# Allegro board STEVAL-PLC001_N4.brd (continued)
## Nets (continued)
Q0.6: C48.2 J14.7 R66.1 U13.16 U13.17
Q0.7: C47.2 J14.8 R63.1 U13.18 U13.19
Q1.0: D16.C J13.1 R40.1 U8.14
Q1.1: D15.C J13.2 R45.1 U8.15
Q1.2: D14.C J11.1 R38.1 U8.16
Q1.3: D13.C J11.2 R37.1 U8.17
RCC_OSC32_IN: R173.2 U27.8
RCC_OSC32_OUT: R180.2 U27.9
RCC_OSC_IN: R178.2 U27.23
RCC_OSC_OUT/TEST: U27.24
RX_EXT: J25.5 R174.1 R175.1
SDO_DAISY: R75.1 R155.2 U2.2
SPI2_ISO_MOSI: R121.2 R154.2
SPI2_MISO: R21.1 R74.1 R126.2 U27.28
SPI2_MORPHO_ISO: J18.15 R72.1 R126.1
SPI2_NSS: R18.1 R68.1 R129.2 U27.73
SPI2_SCK: R69.1 R113.2 R190.2 TP9.1 U2.3 U27.74
SPI5_HOLD: U20.7 U27.36
SPI5_MISO: U20.2 U27.20
SPI5_MOSI: U20.5 U27.21
SPI5_NSS: U20.1 U27.18
SPI5_SCK: U20.6 U27.19
SPI5_WP: U20.3 U27.123
SYS_JTCLK-SWCLK: J23.4 U27.109
SYS_JTDI: J23.8 U27.110
SYS_JTDO-SWO: J23.6 U27.133
SYS_JTMS-SWDIO: J23.2 U27.105
SYS_JTRST: R191.1 U27.134
TX_EXT: J25.2 R177.2 U28.7
UART4-RX: J24.3 R96.2 R109.1
UART4-TX: J22.3 R106.1
UART5_RX: R104.2 R136.1 R138.1 U27.116
USART3_RX: J24.1 R176.2 U28.5
USART3_TX: J22.1 U28.1
USB.OTG_FS_DM: R161.2 U25.2
USB.OTG_FS_DP: R163.2 U25.1
USB.OTG_FS_ID: D44.C(CATHODE) R160.2 U22.4
USB.OTG_FS_VBUS: C92.1 D43.C D46.3 R148.1 R157.2 R192.1 U21.1(OUT) U22.5(VBUS)
USB.OVER_CURRENT: D41.C R146.2 U21.3 U27.87
USB.POWER_SWITCH_ON: R147.2 R192.2 U21.4 U27.88
VZ1: D23.C J12.2 U8.3 U8.18(VZ2)
N15104302: R39.1 U9.2
N15104306: R42.1 U9.3
N15104310: R48.1 U9.4
N15105235: D19.C R41.2 U9.7
N15105303: D20.C R43.2 U9.6
N15105538: R47.1 U8.12
N15105768: R44.1 U8.11
N15112703: D23.A J10.2 J12.1
N15122676: R86.2 U14.4 U15.1
N15122744: C63.1 C66.2 C128.2 D35.C TP11.1 U14.6(VO) U15.2
N15123033: C62.2 C64.2 C65.1 L1.2 L2.1 U14.1
N15123037: D35.A L2.2 U14.8
N15123750: R85.2 U14.2
N15125008: D9.C U3.1
N15125401: D12.C U6.4
N15133396: D17.C R33.2 TP7.1 U7.7
N15133410: D18.C R35.2 U7.6
N15220592: R76.2 R78.1 U13.32
N15439126: D24.A R63.2
N15439189: D25.A R66.2
N15439310: D26.A R67.2
N15439443: D28.A R70.2
N15439617: D30.A R73.2
N15439707: D31.A R77.2
N15439797: D32.A R79.2
N15439887: D33.A R80.2
N15474250: R25.2 U5.9
N15474355: C25.1 U5.10
N15474517: C27.1 U5.15(VBUF2)
N15476731: R23.2 U4.9
N15476759: C19.1 U4.10
N15476871: R24.2 U4.14
N15476899: C21.1 U4.15(VBUF2)
N15484919: R154.1 R155.1 R156.1 U27.27
N15485310: C111.1 C112.2 R168.1 U27.32
N15486514: C102.1 U27.71
N15487467: R157.1 R158.1 U27.101
N15487548: C101.2 U27.106
N15498231: C103.1 C104.1 C105.1 L6.2 R168.2 U27.33
N15498429: R172.2 U28.2
N15498461: R174.2 R175.2 U28.3
N15499136: C124.1 R173.1 Y1.2
N15499220: R178.1 Y2.3(OSC3)
N15499244: C125.1 R180.1 Y1.1
N15499420: R183.2 Y2.1
N15511092: Q1.3 R83.2 U14.7
N15516624: C54.2 R71.2 R72.2 TP10.1 U13.24
N15519714: C50.2 D27.C(CATHODE) R64.1 R65.1 SW1.2 U13.21
N15526476: R46.1 U9.1
N15526659: R32.1 U7.1
N15526663: R31.1 U7.2
N15526669: R34.1 U7.3
N15526673: R36.1 U7.4
N15644326: R71.1 R156.2
N15652884: C98.1 L7.2 U26.1 U26.3
N15653000: D48.A R150.2
N15853888: BT1.1 BT1.2 R184.2
N15937224: R163.1 R164.1 U27.104
N15989509: C53.2 R74.2 R75.2 U13.31
N15989570: C55.2 R68.2 U13.22
N15989574: C57.2 R69.2 U13.23
N16126417: R87.1 U15.5
N16126447: R89.1 U15.13
N16126488: R91.1 U15.21
N16126496: R90.2 U15.14
N16126511: R88.2 U15.6
N16423386: R92.2 U15.22
N16503177: D34.C R81.1
N16514344: C86.1 D39.1 F1.2 Q4.5 Q4.6 Q4.7 Q4.8
N16514352: C87.1 C90.1 D38.C(CATHODE) L4.1 Q4.1 Q4.2 Q4.3(S3) R144.1
N16514548: C90.2 D38.A Q4.4 R144.2 R145.2
N16561780: D11.C U6.1
N16578488: D10.C U3.4
N16596019: R61.1 U12.2
N16596025: R60.1 U12.3
N16605257: C100.2 R184.1 R185.1 U27.6
N16616858: D40.A R142.1
N16634792: D21.A R51.1
N16639460: R62.1 U12.1
N16639519: R59.1 U12.4
N16642965: R57.1 U11.2
N16642967: R58.1 U11.1
N16642969: R56.1 U11.3
N16642971: R55.1 U11.4
N16646826: R53.1 U10.2
N16646828: R50.1 U10.3
N16646830: R54.1 U10.1
N16646832: R49.1 U10.4
N16671237: D15.A R29.2
N16671239: D13.A R27.2
N16671241: D16.A R30.2
N16671243: D14.A R28.2
N16678102: D22.A R52.1
N16736638: D41.A R143.1
N16736836: U22.2 U25.5
N16736872: U22.3 U25.6
N16737152: D47.A R149.2
N16737156: Q5.1 R148.2 R151.1
N16737176: D47.C Q5.3
N16752352: J8.1 R37.2
N16753248: J9.1 R38.2
N16769682: D45.4(C) D46.4(C) L7.1
N16781010: R165.1 U27.48
N16815309: J18.1 R104.1
N16815311: J18.2 R115.2
N16815356: J18.3 R105.1
N16815358: J18.4 R106.2
N16815404: J18.5 R108.1
N16815406: J18.6 R109.2
N16815431: J17.14 R186.2
N16815500: J17.21 R95.1 R96.1
N16815530: J18.11 R113.1
N16815532: J18.12 R118.2
N16815574: J18.13 R121.1
N16815576: J18.14 R122.2
N16815612: J18.16 R123.2
N16815702: J18.19 R189.1
N16815735: J18.22 R131.2
N16815777: J18.24 R134.2
N16815800: J17.28 R187.2
N16815809: J18.26 R135.2
N16815841: J18.28 R136.2
N16815880: J18.30 R138.2
N16815921: J18.31 R190.1
N16815961: J17.35 R98.1
N16815963: J17.36 R188.2
N16815968: J18.34 R139.2
N16815983: J17.37 R99.1
N16816031: R101.1 U19.59
N16816085: R103.1 U19.56
N16816140: R116.1 U19.54
N16816178: R111.1 U19.53
N16816234: R117.1 U19.51
N16816260: R120.1 U19.50
N16816337: R125.1 U19.48
N16816363: R128.1 U19.47
N16816449: R133.1 U19.45
N16816548: D37.A R137.2
N16816568: D36.A R94.2
N16816730: D37.C Q3.3
N16816751: D36.C Q2.3
N16816773: Q2.1 R97.2 R102.1
N16816793: Q3.1 R140.2 R141.1
N16817624: J18.17 R129.1 R130.1
N16822475: C4.1 R1.1 U1.48(_CS)
N16822477: C3.1 R2.1 U1.47
N16822479: C2.1 R3.1 U1.46
N16822481: R4.1 U1.44
N16822499: D1.A U1.41
N16822523: D2.A U1.40
N16822549: R5.1 U1.42
N16822551: D3.A U1.39
N16822575: D4.A U1.38
N16822613: D5.A U1.37
N16822638: D6.A U1.36
N16822654: D7.A U1.35
N16822678: D8.A U1.34
N16822815: R6.1 U1.1
N16822888: J2.2 R8.2
N16822890: R8.1 U1.2
N16822932: R10.1 U1.4
N16823099: J4.2 R10.2
N16823193: C11.1 R13.2 U1.13
N16823195: R15.2 R16.1 U1.14
N16823486: R18.2 R20.2 U2.4
N16823562: R21.2 TP2.1 U2.7
N16919862: R161.1 R162.1 U27.103
N16919990: R152.1 R153.1 U27.35
N16946294: R159.1 R160.1 U27.102
N164994551: R26.2 U5.14
N164999121: D29.C R76.1
N165089721: Q1.1 R84.2
N170697731: J23.7 R191.2
N1681503127: R100.2 U19.28
N1681503130: R114.2 U19.31
N1681503132: R107.2 U19.33
N1681503133: R110.2 U19.34
N1681503135: R112.2 U19.36
N1681503136: R119.2 U19.37
N1681503138: R124.2 U19.39
N1681503139: R127.2 U19.40
N1681503141: R132.2 U19.42

Pads without a net: D45 1; D46 1; J17 1 2 3 4 6 7 9 10 11 12 13 15 17 18 19 23 24 25 26 27 29 30 31 32 38; J18 8 10 18 21 23 25 27 29 33 35 36 37 38; TP16 1; U1 45; U2 5 6 11 12; U4 1 12; U5 1 12; U13 2 26 27 28 29 30; U14 5; U15 41 42; U16 1 16; U19 14 30 57 69 70 73; U22 6 7 8; U24 3; U25 4; U26 4; U29 3

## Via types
v1: diameter 0.4, hole 0.15, TOP to BOTTOM, 414 vias
v2: diameter 0.61, hole 0.33, TOP to BOTTOM, 393 vias
v3: diameter 0.61, hole 0.33, TOP to POWER PLANE, 18 vias

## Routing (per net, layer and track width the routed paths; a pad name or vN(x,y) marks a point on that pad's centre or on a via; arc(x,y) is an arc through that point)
3V3: length 24.2
  POWER PLANE w0.5: v1(68.21,46.98) 67.76,46.52 58.99,46.52 v1(56.71,48.8)
  BOTTOM w0.4: C96.1 70.51,47.99 70.51,48.45 R150.1
  BOTTOM w0.5: v1(68.21,46.98) 68.21,47.79 68.81,48.39 L5.1 69.95,48.6 R150.1 ; v1(70.35,47.24) 70.71,47.6 C96.1 ; v1(56.71,48.8) 53.91,48.8 53.3,49.42 L6.1
  BOTTOM w0.7: U26.5 70.91,46.41 70.85,46.47 70.85,47.13 70.9,47.18 C96.1
5V: length 86.9
  TOP w0.152: v2(43.91,42.8) 43.97,42.86
  TOP w0.3: D45.3 86.51,37.4 v2(86.71,37.2)
  TOP w0.4: L1.1 41.57,41.3 43.13,42.86 43.48,42.86 43.83,42.86 43.97,42.86
  TOP w0.5: U24.6 92.45,30.08 92.45,30.94 93.42,31.92 ; v2(86.71,37.2) 84.79,37.2 84.36,36.77 v2(78.24,36.77)
  BOTTOM w0.3: v2(43.91,42.8) 44.11,43 44.51,43 44.81,43.3 R83.1
  BOTTOM w0.4: v2(43.91,42.8) 43.91,38.6 47.46,35.05 50.42,35.05 57.32,28.15 90.52,28.15 90.76,28.39
  BOTTOM w0.5: v2(86.71,37.2) 89.51,34.4 89.51,31.33 U24.6 90.76,28.39 ; v2(78.24,36.77) 77.95,36.77 77.93,36.75 U21.5
5V_FIELD: length 58.1
  TOP w0.25: D42.C 60.73,19.6 60.34,20 v1(60.34,20.52)
  TOP w0.3: v1(64.29,24.4) 64.32,24.4 C40.1 R52.2 C31.2 R51.2 C35.2 ; D42.C 66.21,20.63 v1(66.44,20.86)
  TOP w0.4: D42.C 66.11,19.5 66.11,18.02 v2(65.89,17.8)
  TOP w0.5: D42.C 67.25,19.6 v2(67.58,19.28)
  BOTTOM w0.25: v1(66.44,20.86) 66.31,20.99 R55.2 ; R59.2 59.87,20.99 v1(60.34,20.52)
  BOTTOM w0.3: 73.31,18.2 72.97,18.2 72.96,18.21 72.46,18.21 72.45,18.2 72.25,18.2 C94.2 ; 64.57,21.91 C43.1 64.65,21.91 65.16,21.4 65.31,21.4 65.72,20.99 R55.2 ; 64.57,21.91 65.11,22.45 65.11,23.58 v1(64.29,24.4) ; 64.57,21.91 64.43,21.91 R62.2 ; R54.2 75.27,20.08 75.3,20.08 75.66,19.73 C95.1 ; v2(67.58,19.28) 67.58,19.38 68.65,20.45 68.74,20.45 69,20.71 69.33,21.04 R58.2 R49.2
  BOTTOM w0.4: U23.3 73.62,17.89 72.91,18.6 72.76,18.6 69.71,18.6 68.91,17.8 v2(65.89,17.8)
  BOTTOM w0.5: C95.1 77.81,21.67 U9.8 77.81,25.9 78.31,26.4 83.56,26.4 84.06,25.9 U7.8
  BOTTOM w0.6: U23.3 75.86,18.84 C95.1
24V: length 13.4
  TOP w1.2: C84.1 15.26,15.95 15.26,18.14
  TOP w3: J19.2 13.11,5.66 C84.1
24V_FIELD: length 97.6
  TOP w0.152: L4.2 13.01,53.6 ; v2(14.88,56.14) 13.26,56.14 13.01,55.89 ; v2(13.01,56.12) 12.43,56.12 12.41,56.09 v2(11.13,56.09) ; 13.01,53.6 v2(11.17,51.76) ; 13.01,53.6 13.01,53.5 ; 13.01,53.49 v2(14.83,51.67) ; v2(77.31,17.6) 78.08,18.37 78.08,18.44 ; 78.08,18.44 v2(78.91,17.6) ; 78.08,18.44 78.08,19.26 ; 13.01,53.47 13.01,52.56
  TOP w0.2: U8.13 69.53,14.93 v1(69.66,14.8)
  TOP w0.3: v1(73.95,14.01) 73.83,13.89 C36.2 73.2,13.86 C34.2 ; 33.57,102.21 33.57,104.14 v1(33.11,104.6) ; 33.57,102.21 R15.1 ; 33.57,102.21 34.87,102.21 R13.1 ; v1(68.47,11.48) 68.29,11.66 R30.1 ; v2(72.51,11.2) 72.67,11.36 72.67,11.49 R29.1 ; C46.2 42.7,22.79 41.61,21.7 U13.TAB4
  TOP w0.4: C89.1 v2(13.01,51.8)
  TOP w0.5: 78.08,20.14 C37.1 79.62,22.2 v2(79.91,22.2) ; 78.08,20.14 78.08,19.26 ; 78.08,20.14 78.82,20.14 ; L4.2 13.01,54.9 ; 13.01,54.9 v2(13.01,56.12) ; 13.01,54.9 12.6,55.31 11.91,55.31 v2(11.13,56.09) ; 13.01,54.9 13.37,55.26 14,55.26 v2(14.88,56.14) ; 78.08,19.26 77.97,19.26 77.31,18.6 v2(77.31,17.6) ; 78.08,19.26 78.08,19.26 78.91,18.43 v2(78.91,17.6) ; R27.1 83.57,11.91 82.95,11.29 79.76,11.29 78.85,12.2 R28.1 77.87,12.68 77.57,12.98 v1(77.06,12.98) ; v2(13.01,51.8) 13.01,52.56 12.85,52.72 12.85,53.31 13.01,53.47 13.01,53.5 12.06,53.5 11.17,52.61 v2(11.17,51.76) ; v2(8.46,60.02) 7.88,60.02 R142.2 ; J26.2 88.67,11.07 88.49,11.25 C130.1 ; 13.01,53.63 13.16,53.48 13.81,53.48 14.83,52.46 v2(14.83,51.67)
  BOTTOM w0.152: 20.69,30.34 19.77,30.34 19.51,30.6
  BOTTOM w0.3: v2(72.51,11.2) 69.3,11.2 69.02,11.48 v1(68.47,11.48)
  BOTTOM w0.5: v2(21.51,29.52) 19.84,31.19 ; C88.1 19.41,30.75 19.84,31.19 ; C88.1 18.46,30.7 18.09,31.07 17.92,31.07 v2(17.25,31.74) ; C88.1 19.51,30.6 19.51,29.64 v2(20.62,28.53) ; v2(7.51,56.93) 7.51,57.46 6.46,58.52 6.87,58.92 ; v1(77.06,12.98) 76.83,12.98 76.66,12.81 U23.1 74.23,12.14 C93.1 74.23,9.94 74.58,9.59 v2(74.58,8.15) ; 6.87,58.92 v2(6.87,60.1) ; 6.87,58.92 7.36,58.92 v2(8.46,60.02) ; 19.84,31.19 19.66,31.37 19.66,31.4 v2(18.29,32.77)
  vias: v2(17.16,22.05) v2(17.22,20.81) v2(17.22,19.6) v2(17.22,18.38) v2(17.24,17.1) v2(17.21,16.09) v2(18.36,22.05) v2(18.41,20.81) v2(18.44,19.6) v2(18.41,18.38) v2(18.42,17.1) v2(18.42,16.09) v2(19.56,22.05) v2(19.62,20.81) v2(19.62,19.6) v2(19.62,18.38) v2(19.64,17.1) v2(19.61,16.09) v2(20.76,22.05) v2(20.81,20.81) v2(20.84,19.6) v2(20.81,18.38) v2(20.82,17.1) v2(20.82,16.09) v2(22.01,22.1) v2(22.01,16.09) v2(22.07,20.86) v2(22.07,19.65) v2(22.07,18.43) v2(22.11,17.2) v2(23.21,22.1) v2(23.26,20.86) v2(23.26,18.43) v2(23.26,16.04) v2(23.29,19.65) v2(23.31,17.2) v2(24.41,22.1) v2(24.47,20.86) v2(24.47,19.65) v2(24.47,18.43) v2(24.51,17.2) v2(24.47,16.04) v2(25.61,22.1) v2(25.66,20.86) v2(25.66,18.43) v2(25.66,16.04) v2(25.69,19.65) v2(25.71,17.2) v2(26.86,22) v2(26.92,20.76) v2(26.92,19.55) v2(26.92,18.33) v2(26.87,17.05) v2(26.87,16.04) v2(28.06,16.04) v2(28.06,22) v2(28.11,20.76) v2(28.14,19.55) v2(28.11,18.33) v2(28.09,17.05) v2(29.26,22) v2(29.32,20.76) v2(29.32,19.55) v2(29.32,18.33) v2(29.34,17.05) v2(29.31,16.04) v2(30.46,22) v2(30.51,20.76) v2(30.54,19.55) v2(30.51,18.33) v2(30.52,17.05) v2(30.52,16.04) v2(31.61,22.05) v2(31.66,20.81) v2(31.66,18.38) v2(31.69,19.6) v2(31.67,17.1) v2(31.67,16.09) v2(34.77,23.39) v2(34.77,22.17) v2(34.77,20.95) v2(34.77,19.94) v2(35.98,23.39) v2(35.98,21.97) v2(35.98,19.94) v2(36.59,20.75) v2(37,19.94) v2(37.61,23.39) v2(37.81,21.56) v2(37.81,20.75) v2(39.03,23.39) v2(39.23,22.37) v2(39.23,20.95) v2(39.43,19.94) v2(40.45,23.39) v2(40.65,22.17) v2(40.65,20.95) v2(40.65,19.94)
GND_CLT1: length 41.5
  TOP w0.2: v1(28.71,91.6) 28.61,91.5 C1.2 28.69,91.01 C2.2 ; v1(27.71,91.86) 27.8,91.95 U1.43 ; v1(26.51,90.2) 26.95,90.2 R5.2 ; C4.2 33.92,93.14 C6.1 v1(34.51,93.18)
  TOP w0.3: v1(32.11,91.6) 32.12,91.59 C3.2 ; TP14.1 25.48,88.71 R5.2 25.94,90.19 25.61,89.86 22.45,89.86 v1(18.62,93.69)
  TOP w0.5: C14.2 v1(46.76,91.71) 46.76,95.14 47.99,96.37 TP4.1 ; v1(39.83,97.44) v1(39.83,95.86) C5.2
  BOTTOM w0.2: v1(28.71,91.6) 28.45,91.86 v1(27.71,91.86) 26.51,90.66 v1(26.51,90.2)
  BOTTOM w0.3: R194.1 20.07,95.02 19.95,95.02 v1(18.62,93.69) ; C129.2 33.9,93.79 v1(34.51,93.18) 33.69,93.18 v1(32.11,91.6)
  BOTTOM w0.4: v2(38.71,94.87) 38.71,94.4 38.77,94.34 U2.9
GND_EARTH: length 28.9
  TOP w3: C84.2 3.11,18.23 3,18.35 3,20.95 3.11,21.07 C91.1
  BOTTOM w3: J20.1 3.01,11.75 3.11,11.85 C84.2 C91.1
GND_EXT: length 17.4
  TOP w0.3: 89.41,86.85 v2(90.22,86.85) 90.22,87.7 91.49,88.98 94.62,88.98
  TOP w0.4: 94.62,88.98 95.71,88.98 J25.4 J25.3
  BOTTOM w0.152: R177.1 v2(90.22,86.85)
  BOTTOM w0.3: U28.4 91.06,93.5 93.05,91.52 94.79,91.52
  BOTTOM w0.4: 94.79,91.52 95.71,91.52 J25.3
GND_FIELD: length 321.5
  TOP w0.152: 6.51,19.65 v2(7.6,19.65) 7.6,19.81 7.67,19.88 ; 6.51,19.65 6.15,19.65 ; 6.51,19.65 6.51,19.5 7.1,18.91 v2(7.73,18.91) ; 27.32,98.12 27.32,97.64 26.8,97.12 26.8,96.61 U1.49 29,97.31 29,98.12 29.3,98.42
  TOP w0.2: 29.3,98.42 29.3,99.25 29.31,99.26 ; 27.8,93.33 27.55,93.57 27.55,94.07 27.8,94.32 27.8,94.75 27.55,95 U1.49 28.93,94.48 29.85,94.48 30.21,94.11 U1.3 ; C11.2 31.97,98.34 31.74,98.11 U1.11 U1.12 ; U13.3 33.36,20.65 32.91,20.2 v2(32.91,19.05) ; 26.8,99.25 26.8,98.64 27.32,98.12 ; 71.58,12.94 R45.2
  TOP w0.3: 71.57,12.94 71.51,12.94 71.49,12.92 ; 71.57,12.94 C34.1 ; 71.57,12.94 71.71,12.8 v1(71.71,12.39) ; C12.1 v1(24.66,102.78) ; C18.1 19.96,102.55 19.91,102.6 v1(19.91,102.87) ; C13.1 v1(23.11,102.85) ; C34.1 72.59,12.94 ; C34.1 72.44,12.97 C36.1 ; C86.2 3.1,42.99 2.51,42.4 v2(2.51,42.3) ; v1(66.66,13.55) 67.06,13.14 R40.2 ; C17.1 v1(21.56,102.85) ; C46.1 v2(43.71,24.5) ; C7.1 v1(31.11,102.6) ; R16.2 v1(32.76,102.65) ; C9.1 v1(27.91,102.78) ; C10.1 v1(26.31,102.75) ; C8.1 v1(29.51,102.6) ; U8.20 74.09,16.21
  TOP w0.35: U8.20 U8.19
  TOP w0.4: D33.C D32.C D31.C 35.08,13.8 ; 85.21,18.7 84.45,19.46 C37.2 83.7,21.4 v2(82.71,21.4) ; D28.C 40.06,14.6 39.91,14.75 C49.1 ; D28.C D30.C 35.16,14.83 35.71,15.38 C58.1 ; D28.C D26.C D25.C ; R195.2 v1(89.73,23.29)
  TOP w0.5: v2(13.91,49.8) 13.8,49.69 C89.2 ; D8.C D7.C D6.C D5.C 32.58,107 32.53,107.05 D4.C D3.C 26.14,107.05 25.69,106.6 v1(25.51,106.6) ; D24.C 55.16,14.15 v2(54.51,14.8) ; v2(2.87,45.6) 2.91,45.6 2.92,45.59 R145.1 ; v2(46.23,12.99) 45.41,13.8 ; v2(86.03,22.4) 84.45,20.82 C37.2 ; 74.09,21.24 U8.1 73.75,21.48 ; v2(64.93,14.8) 64.93,14.82 65.41,15.3 D42.A ; C87.2 5.18,39.86 6.51,41.2 v2(6.51,41.8) ; C87.2 4.4,39.98 4.4,41.11 4.04,41.46 v2(3.59,41.46) ; C87.2 5.18,37.93 ; v1(22.46,106.95) 22.31,107.1 D2.C 17.27,107.1 17.23,107.15 D1.C ; 37.68,25.02 U13.TAB2 37.94,25.02 ; v3(33.31,15.35) 33.51,15.15 33.73,15.15 35.08,13.8 D30.C ; J26.1 83.59,8.73 86.99,12.13 C130.2 ; 5.18,37.93 v2(6.51,36.6) ; 5.18,37.93 5.18,37.86 3.91,36.6 v2(3.73,36.6) ; 73.75,21.48 73.75,21.41 74.51,20.65 v1(74.51,19.8) 74.51,16.24 U8.20 v2(74.53,15.82) ; 73.75,21.48 U8.2 ; C47.1 C48.1 C49.1 C51.1 C52.1 C56.1 C58.1 C59.1 ; D40.C 7.21,63.9 6.91,63.6 6.91,63.3 v2(6.74,63.3) ; 24.66,13.8 v2(24.01,13.15)
  TOP w1: 6.15,19.65 6.15,21.98 v2(6.11,22.01) ; U13.TAB3 v2(42.11,25.02) ; U13.TAB1 v2(33.51,25.02)
  TOP w1.4: U13.TAB1 37.68,25.02 ; U13.TAB3 37.94,25.02
  TOP w3: 6.15,19.65 8.02,17.78 J19.1
  POWER PLANE w0.5: 4.9,36.88 5.18,37.15 5.18,40.46 v2(6.51,41.8) ; 4.9,37.72 6.02,36.6 v2(6.51,36.6) ; 4.9,37.72 4.9,40.61 4.04,41.46 v2(3.59,41.46) ; 4.9,37.72 3.79,36.6 v2(3.73,36.6)
  POWER PLANE w1: 4.9,37.72 4.9,32.41 6.11,31.2 14.91,31.2 15.31,30.8 15.31,30.4 14.91,30 5.11,30 4.71,29.6 4.71,29.2 5.11,28.8 16.11,28.8 16.51,28.4 16.51,27.8 16.31,27.6 6.71,27.6 6.31,27.2 6.31,26.8 6.71,26.4 10.71,26.4 11.11,26 11.11,25.4 10.71,25 8.31,25 8.11,24.8 8.11,24 6.83,22.72 6.82,22.72 v2(6.11,22.01)
  LOGIC_PLANE w1: 6.11,21.28 v2(6.11,22.01)
  BOTTOM w0.152: 15.41,34.7 15.87,34.24 16.42,34.24 v2(17.18,35) ; 15.41,34.7 15.11,35 ; 15.41,34.7 15.41,33.74 ; v2(14.31,37.64) 14.54,37.64 15.69,36.5 15.69,36.17 C88.2
  BOTTOM w0.3: R194.2 22.15,95.59 21.98,95.59 21.98,95.64 ; C94.1 73.03,16.94 73.69,16.28 74.07,16.28 v2(74.53,15.82) ; 25.52,95.19 v2(25.52,95.04)
  BOTTOM w0.5: 25.12,95.59 22.15,95.59 ; v1(25.51,106.6) 23.46,106.6 23.11,106.95 v1(22.46,106.95) 20.66,106.95 17.11,103.4 17.11,100.4 21.92,95.58 R194.2 ; v2(12.45,35.61) 13.37,35.61 13.38,35.6 14.51,35.6 ; 15.11,35 C88.2 14.51,35.6 ; 15.11,35 15.08,34.97 15.08,34.07 15.41,33.74 v2(15.41,32.86) ; 15.11,35 v2(17.18,35) ; 14.51,35.6 14.31,35.8 v2(14.31,37.64) ; C85.2 6.46,64.05 6.74,63.77 v2(6.74,63.3) ; C85.2 6.46,65.95 6.91,66.4 v2(6.91,66.47) ; C85.2 7.79,64.88 ; v2(9.22,66) 8.91,66 7.79,64.88 ; 7.79,64.88 v2(9.23,64.88) ; v2(15.71,23.85) 17.19,23.85 18.23,24.89 ; 18.23,24.89 C45.2 20.4,24.89 21.24,25.73 v2(21.24,26.6) ; 18.23,24.89 17.36,25.75 v2(17.36,26.55) ; v2(76.66,11.45) 75.98,10.78 C93.2
  BOTTOM w0.8: 25.52,95.19 25.12,95.59 25.12,96.01 25.71,96.6
  vias: v2(25.52,97.88) v2(25.51,96.35) v2(25.52,93.82) v2(26.74,97.88) v2(26.74,95.04) v2(26.74,93.82) v2(26.91,96.35) v2(28.16,97.88) v2(28.16,96.46) v2(28.16,95.24) v2(28.16,93.82) v2(29.58,97.88) v2(29.58,96.66) v2(29.58,95.24) v2(29.58,93.82) v2(82.61,19.5) v2(82.67,18.26) v2(83.71,20.6) v2(83.81,19.5) v2(83.86,18.26) v2(85.01,19.5) v2(85.07,18.26) v2(85.31,20.6) v2(86.21,19.5) v2(86.26,18.26)
GND_LCD: length 23.3
  TOP w0.152: 32.46,38.72 U14.9
  TOP w0.2: 30.11,38.72 29.89,38.5 29.85,38.5 R86.1 ; 30.11,38.72 29.96,38.72 29.6,39.09 R85.1 ; 30.11,38.72 U14.3
  TOP w0.3: C66.1 v1(36.37,42.34) 36.36,42.35 ; R86.1 R85.1 ; 32.46,38.21 32.46,37.73 32.16,37.43 30.67,37.43 v2(29.59,36.35) ; 32.46,38.21 32.46,38.72 ; 32.46,38.21 33.02,37.65 33.37,37.65 v2(33.83,37.19) ; C128.1 34.56,45.25 34.31,45 v1(34.31,44.7) ; v1(37.86,43.5) 38.63,42.73 Q1.2 39.01,42.73 39.38,42.37 39.38,40.84 39.37,40.84 C62.1 C64.1 39.37,38.09 L3.2 39.76,37.65 39.14,37.03 39.14,36.98 38.46,36.3 C65.2
  TOP w0.4: C63.2 33.08,45.39 C128.1 ; U14.9 32.14,38.72 U14.3
GND_LOGIC: length 321.4
  TOP w0.152: v1(40.31,33.28) C57.1 ; v1(44.91,33.31) 44.91,32.72 ; v1(41.21,33.28) C55.1 ; C53.1 34.66,32.79 v1(34.09,32.22) ; C50.1 v1(43.06,33.28)
  TOP w0.16: v3(46.33,59.83) 46.32,59.82 46.05,59.82 45.84,59.61 45.83,59.61 45.66,59.45 45.66,59.43 45.47,59.24 U17.17 ; U15.3 v1(44.39,51.82)
  TOP w0.2: U13.1 v2(33.06,29.05) ; C54.1 v1(38.66,33.28)
  TOP w0.22: v1(39.11,89.4) 38.15,90.36 36.27,90.36 v1(35.7,89.79)
  TOP w0.25: 93.83,52.31 U22.1 v3(94.96,52.3) 95.89,52.3 96.4,51.79 96.4,50.92 v1(95.8,50.32)
  TOP w0.3: v2(38.01,58.05) 37.36,57.39 D49.A 36.55,57.42 36.05,57.92 36.05,58.16 35.07,59.15 ; v1(62.86,62.88) 62.77,62.88 62.45,63.2 C127.1 ; C67.1 36.25,46.94 36.11,46.8 v1(35.51,46.8) ; U15.36 60.89,51.96 60.52,51.59 v1(60.31,51.59) ; U15.35 60.39,52.19 60.34,52.14 60.34,52.06 60.16,51.89 60.05,51.89 59.76,51.6 v1(59.11,51.6) 57.63,51.6 57.39,51.84 U15.29 ; U16.17 v1(51.82,59.73) ; v2(89.11,49.8) 89.11,51.91 89.48,52.28 D43.A ; C103.2 v1(56.92,65.61) ; L3.1 40.37,36.71 v1(40.37,36.85) ; 93.83,52.31 93.59,52.31
  TOP w0.4: v2(51.17,31.46) SW1.1 ; SW1.1 v2(51.17,28.25) ; SW1.1 v2(49.81,29.85) ; SW1.1 v2(52.6,29.85) ; U18.17 v2(38.01,58.05) ; C61.2 v2(45.12,30.05)
  TOP w0.5: C24.1 62.29,88.8 v1(62.08,88.59) ; C60.2 44.61,28.78 v2(45.04,29.2)
  POWER PLANE w0.152: v1(49.41,68.1) 49.41,66.56 49.38,66.53 v1(49.38,66.05) ; v1(42.11,70.2) v1(42.11,71.75)
  POWER PLANE w0.16: v1(43.94,60.4) 44.15,60.61 46.14,60.61 46.33,60.42 v3(46.33,59.83)
  POWER PLANE w0.3: v1(82.9,79.1) 82.9,79.65 82.91,79.66 82.91,82 v1(83.31,82.4) ; v1(42.35,44.29) 42.35,45.94 42.94,46.53 v1(42.94,47.08) ; v1(50.12,73.7) 50.6,74.19 50.7,74.19 52.01,75.5 v2(53.01,75.5) ; v1(53.16,68.5) 53.55,68.11 54,68.11 v1(55.29,66.83) ; v1(44.3,36.36) 43.14,36.36 v1(42.42,35.64)
  BOTTOM w0.152: R31.2 v2(85.31,33.85) ; v1(43.01,75.55) 43.36,75.2 U19.58 ; R42.2 80.36,33.65 80.35,33.66 v2(80.35,33.85) ; U19.52 43.31,78.2 v1(42.91,78.6) ; U27.83 v2(58.86,81.3) ; 64.72,32.91 v2(64.76,32.95) ; v2(79.07,33.85) 79.07,33.62 79.11,33.58 R39.2 ; v1(64.91,81.35) 64.36,81.9 U27.94 ; v2(65.86,31.35) 65.86,30.85 65.86,30.85 ; 61.24,46.93 U20.4 ; U19.12 v1(32.11,66.7) ; v2(76.31,40.89) 76.31,40.4 76.35,40.36 R147.1 ; 53.01,46.7 C110.2 ; R34.2 86.51,33.6 86.31,33.8 v2(86.31,33.85)
  BOTTOM w0.16: v1(43.16,80.9) 43.46,81.2 U19.46 ; U19.44 44.81,82.2 45.01,82.4 v1(45.15,82.4) ; U19.72 42.91,68.2 v1(42.71,68) ; C111.2 54.77,58 v1(54.68,58) ; U19.6 v1(33.96,63.7)
  BOTTOM w0.18: U27.51 52.9,70.5 53.11,70.29 v1(53.11,69.95) ; v1(47.31,64.2) 47.07,63.96 C71.2 ; C109.1 93.15,72.47 J23.3
  BOTTOM w0.2: U19.78 44.08,65.1 43.55,65.1 43.31,64.86 43.31,62.54 43.65,62.2 ; C117.1 48.91,70.44 51.92,70.44 U27.51 ; Q5.2 93.06,60.17 93.6,60.71 R151.2 ; 43.94,60.67 43.94,60.96 U19.86 43.51,61.2 ; 43.94,60.67 v1(43.94,60.4) ; 43.94,60.67 43.51,61.1 43.51,61.2 ; v1(75.6,86.31) C29.1 ; 42.94,47.17 v1(42.94,47.08) ; 42.94,47.17 42.51,47.6 R87.2 ; 42.94,47.17 R88.1 ; v1(59.51,57.4) 59.24,57.13 Y2.2 ; U27.31 v1(56.36,62.6) ; 43.51,61.2 43.31,61.4 43.31,62 43.51,62.2 43.65,62.2 ; U11.5 65.86,31.86 64.8,32.91 C44.2 ; C111.2 C112.1 C106.2 C115.1 ; 43.65,62.2 U19.84 ; C98.2 69.95,43.71 U26.2 ; C73.2 v1(46.92,66.33) ; C102.2 C119.1 47.71,81 47.66,81.05 R125.2 ; v2(81.21,89.5) 81.21,88.88 80.84,88.51 U6.5 ; 64.01,86.36 63.31,85.66 63.31,84.86 64.36,83.81 U27.94 ; C114.1 65.56,58.8 65.6,58.76 v1(65.71,58.76) C125.2 ; v1(69.44,59.08) 69.24,58.88 69.13,58.88 C124.2 C100.1 ; C82.1 64.01,55.45 63.91,55.55 v1(63.91,57) ; U27.107 70.86,83.65 v1(70.71,83.8) ; R93.2 v1(44.51,47) ; U27.120 v2(70.54,75.5)
  BOTTOM w0.22: R141.2 R102.2 v1(35.7,89.79)
  BOTTOM w0.25: R176.1 91.97,90.92 90.69,92.2 88.71,92.2 87.91,93 87.91,95.31 87.5,95.72 87.5,96.22 87.5,96.4 R172.1 ; U27.83 58.86,84.35 59.11,84.6 59.11,84.71 59.23,84.83 59.23,85.01 59.26,85.04 C120.1 ; U27.130 75.14,70.5 75.31,70.67 75.34,70.67 75.46,70.8 C113.1 76.16,70.79 C107.1 ; 82.51,75.2 82.16,74.85 J18.9 ; U19.38 v2(33.91,79.7) ; v2(34.26,77.35) 33.6,76.7 U19.32
  BOTTOM w0.3: SW2.2 34.94,58.63 ; SW2.2 35.44,58.78 35.38,58.78 35.09,59.07 35.09,59.13 35.07,59.15 ; SW2.2 35.59,59.28 ; 34.94,58.63 v1(34.31,58) ; 34.94,58.63 34.28,58.63 v1(34.02,58.89) ; v2(83.23,74.84) 83.13,74.84 83.12,74.85 82.16,74.85 ; v2(82.91,70.8) 82.45,71.26 78.43,71.26 C107.1 ; v2(70.64,88.25) 70.21,88.25 70,88.46 U3.5 ; U27.16 63.86,62.45 63.51,62.8 63.49,62.8 63.41,62.88 v1(62.86,62.88) ; 47.66,63.8 47.66,63.85 v1(47.31,64.2) ; 47.66,63.8 50.31,63.8 50.51,64 50.65,64 50.66,64.01 51.16,64.01 51.17,64 U27.38 ; 47.66,63.8 47.17,63.8 C71.2 47.55,63.7 C116.1 ; R171.2 83.71,63.7 85.26,62.15 J18.20 ; 59.91,52.2 60.31,51.8 v1(60.31,51.59) 59.67,51.59 59.66,51.6 ; 59.91,52.2 59.91,51.85 59.66,51.6 ; 59.91,52.2 C126.2 C105.2 ; C118.1 48.35,75.7 48.66,75.39 49.91,75.39 50.02,75.5 U27.61 v2(53.01,75.5) ; U25.3 v2(89.11,49.8) ; C96.2 71.82,47.26 71.71,47.15 71.71,47.05 v1(71.66,47) ; C108.1 76.97,61.66 76.62,61.31 75.5,61.31 v1(75.11,61.7) ; U27.130 71.71,70.5 v2(71.51,70.3) ; C104.2 57.89,53.61 57.89,53.22 58.62,52.49 C105.2 ; 35.59,59.28 35.59,59.79 v1(35.24,60.14) ; 35.59,59.28 v1(36.31,60) ; U10.5 71.86,30.8 71.81,30.85 v2(71.81,31.3) ; 76.15,71.75 76.05,71.65 C113.1 ; v1(73.71,37.4) 74.01,37.7 U21.2 ; v1(44.39,51.82) 43.55,52.65 C68.2 ; 59.66,51.6 v1(59.11,51.6) 59.11,51.8 59.06,51.85 C105.2 ; v2(30.37,85.8) 30.51,85.8 30.54,85.83 Q3.2 ; v2(85.84,48.05) 85.84,47.21 86.14,46.91 J18.32 ; U19.78 43.26,65.2 42.96,65.5 v1(42.96,66.35) ; R91.2 R92.1 R193.2 ; R91.2 v1(47.51,47.2) ; R91.2 R90.1 R89.2 R93.2 ; v2(93.04,46.61) 92.98,46.55 C92.2 ; D44.A v1(95.8,50.32) ; U2.8 38.77,89.05 v1(39.11,89.4) ; v2(59.87,48.26) 60.33,47.79 60.44,47.79 U20.4
  BOTTOM w0.4: 29.51,78.45 29.51,78.44 C78.2 ; v1(73.31,87.87) 73.06,87.87 C30.2 ; R117.2 R120.2 C79.2 R125.2 R128.2 v2(47.07,82.65) ; C16.2 50.17,88.54 50.16,88.55 v2(50.16,88.94) ; 64.01,86.36 C121.1 ; C77.2 47.23,76.25 47.48,76 C118.1 ; C77.2 C76.2 R103.2 R101.2 ; C77.2 R116.2 R111.2 ; J18.20 v2(89.56,62.15) 90.34,62.15 92.33,60.17 Q5.2 ; v2(70.71,50.6) 69.83,50.6 68.84,51.59 ; R176.1 v2(92.77,86.9) ; 26.91,77.7 27.01,77.6 R110.1 ; C78.2 R110.1 ; C78.2 R112.1 R119.1 R124.1 R127.1 R132.1 C81.2 C80.2 29.5,84.66 v2(29.06,85.1) ; R110.1 R107.1 ; R107.1 27.7,76.8 27.1,76.2 v2(25.59,76.2) ; R107.1 R114.1 C75.2 R100.1 v2(29.5,73.4) ; C97.2 v1(60.17,49.69) ; v2(35.11,85.23) Q2.2 ; J18.9 77.17,74.85 C123.1 ; C108.1 R181.2
  BOTTOM w0.5: D48.C 93.83,35.2 91.61,32.98 91.61,31.78 ; U12.5 59.81,31.16 59.76,31.2 v2(59.76,31.3) ; C122.1 C101.1 72.36,87.48 72.35,87.49 72.35,88.16 72.36,88.17 72.36,88.42 C30.2 ; v2(29.06,65.98) 29.06,65.65 29.45,65.26 C72.2 ; 64.01,86.36 63.06,87.31 63.06,87.77 62.64,88.19 C22.2 62.27,88.4 v1(62.08,88.59) ; C16.2 50.76,87.56 C15.2 ; v2(71.06,32.1) 71.21,32.1 71.22,32.09 C41.2 ; C70.2 29.45,62.46 29.31,62.6 v2(29.31,62.99) ; 70,42.41 69.96,42.45 U26.2 69.96,44.2 70.4,44.64 v2(70.4,44.79) ; C74.2 29.45,68.31 28.98,68.77 v2(28.98,68.96) ; v2(68.99,42.36) 69.21,42.14 69.74,42.14 C98.2 ; v2(54.4,48) 54.31,48 53.01,46.7 v2(54.41,46.7) ; C69.2 28.97,61 28.83,61.14 v2(28.66,61.14) ; v2(27.46,60.52) 26.5,59.56 J17.22 v2(25.59,60.74) ; v2(23.49,78) 23.76,78 24.02,77.74 24.22,77.74 24.62,77.34 J17.8 26.55,77.34 26.96,76.94 27.57,76.94 27.7,76.8 ; v2(25.59,63.24) J17.20 v2(27.7,62.1) ; R117.2 R111.2 ; C42.2 70.25,33.06 70.26,33.05 v2(70.45,33.05)
  BOTTOM w0.6: C99.2 68.84,50.22 C83.2
  vias: v2(53.67,40.65) v2(53.67,39.43) v2(54.86,41.86) v2(54.86,39.43) v2(54.89,40.65) v2(56.07,41.86) v2(56.07,40.65) v2(56.07,39.43)
GND_SIGNAL: length 39.7
  TOP w0.152: v1(67.66,22.4) 67.66,22.79 C35.1
  TOP w0.16: C33.1 C32.1 72.91,24.73 73.09,24.91 v1(73.09,25.6)
  TOP w0.17: 66.26,22.85 66.26,22.75 66.11,22.6 v1(66.11,22.55) ; v1(64.14,23.09) 64.52,23.09
  TOP w0.25: v1(69.71,22.45) 69.71,22.4 69.53,22.22 U8.8
  TOP w0.3: 70.88,24.01 70.72,24.01 v1(70.51,23.8) ; 70.88,24.01 C38.1 ; 70.88,24.01 70.73,24.16 70.28,24.16 70.13,24.01 C39.1 ; 64.52,23.09 C40.2 ; v1(67.91,12.45) 68,12.54 68,12.93 R44.2 68.56,13.49 R47.2 ; 66.26,22.85 C31.1
  TOP w0.4: R195.1 v1(87.04,22.01)
  TOP w0.8: v2(58.11,16.94) 66.66,16.94 v2(66.71,17) 68.36,18.65 U8.21
  BOTTOM w0.17: v1(64.14,20.64) 64.26,20.64 C43.2
  BOTTOM w0.3: U9.5 v1(81.62,25.41) ; U7.5 v1(87.87,23) ; v2(58.11,16.94) 58.97,16.94 63.46,12.45 v1(67.91,12.45)
  BOTTOM w0.5: v2(76.47,22.49) 76.47,22.32 75.86,21.71 C95.2
VDD: length 636
  TOP w0.152: 77.01,66.65 77.31,66.35 v1(77.51,66.35) ; 59.27,86.69 59.26,86.71 v1(59.26,86.75) ; 43.35,30.04 C61.1
  TOP w0.16: v1(43.91,51.2) 44.46,51.2 44.89,51.63 U15.4 ; 67.11,48.25 67.4,47.96 67.4,47.4
  TOP w0.2: 71.42,56.14 v2(70.81,56.75) ; v1(56.86,62.91) 58.18,64.23 R182.2 ; R170.1 76.97,66.61 77.01,66.65 ; v1(75.11,58.4) 75.11,59.03 74.71,59.43 ; v1(85.66,55.99) 86.12,56.45 87.79,56.45 87.84,56.4 v1(90.91,56.4)
  TOP w0.25: 77.01,71.65 77.11,71.75 ; 77.01,71.65 76.92,71.74 v2(76.92,77.39) ; 77.01,71.65 78.36,71.65 78.26,71.75 v1(77.86,71.75) 77.83,71.75 ; 77.01,63.93 77.08,64 v1(77.71,64) ; 76.49,62.2 76.31,62.38 75.58,62.38 v1(75.32,62.63) ; 74.85,85.36 74.92,85.43 v1(75.54,85.43) ; v1(75.51,70.2) 76.66,70.2 77.01,69.85
  TOP w0.3: 48.96,70.9 49.17,70.9 C117.2 v1(49.81,71) ; C78.1 30.72,78.45 ; 30.67,65.25 30.62,65.2 v2(30.37,65.2) ; v2(18.11,79.9) 17.45,79.9 16.15,81.2 R94.1 R137.1 ; 77.01,69.85 76.96,69.8 ; 50.5,40.1 45.04,45.55 39.5,45.55 37.19,47.86 C67.2 36.46,48.45 v1(36.31,48.6) ; 30.72,75.15 31.01,75.15 v2(31.06,75.2) ; 49.02,81.54 52.37,81.54 v2(53.21,80.7) ; v1(90.91,56.4) 90.91,55.43 90.61,55.13 90.61,54.3 v1(91.11,53.8) ; 77.07,71.75 76.96,71.64 76.96,70.8 ; v1(46.15,80.2) 49.02,80.2 ; 77.02,65.61 77.01,65.6
  TOP w0.4: v2(48.31,65.24) 48.31,65.97 48.28,66 ; v1(42.71,29.8) 42.96,30.05 C61.1 43.31,30.01 43.31,29.89 42.62,29.2 42.26,29.2 U13.20 ; 67.21,33.75 67.31,33.65 67.31,33.4 v2(69.12,31.6) ; 67.21,33.75 67.11,33.85 v2(64.59,31.32) ; 67.21,33.75 v2(71.91,33.75) 72.71,33.75 v2(75.16,31.3) ; C60.1 v2(42.31,27.03) 30.7,27.03 28.31,24.64 D34.A 28.31,24.25 27.75,23.69 25.47,23.69 D29.A ; 73.52,86.69 73.52,87.02 74.12,87.63 74.12,88.01 74.36,88.25 ; v2(64.48,85.07) 64,85.55 64,86.69 ; 77.02,65.08 77.02,65.61 ; 74.36,88.25 74.59,88.48 76.3,88.48 76.91,87.87 v2(76.91,87.16) 77.41,87.66 77.41,89.3 78.31,90.2 87.11,90.2 v2(88.11,91.2) ; 74.36,88.25 74.84,87.77 v2(75.33,87.77) ; 48.96,76.25 49.06,76.25 v2(49.31,76) ; v2(73.36,39.85) 67.16,39.85 67.11,39.9
  TOP w0.5: v1(46.16,76.25) 46.92,76.25 46.92,76.25 48.96,76.25 ; 77.07,74.04 77.07,71.75 77.11,71.75 ; J23.1 94.16,73.78 93.54,73.78 91.31,71.55 78.03,71.55 77.83,71.75 ; v2(31.11,84.8) 31.11,84.75 31.79,84.07 ; 76.49,62.2 77.01,61.68 ; v2(70.83,84.64) 70.83,85.4 71.46,86.04 71.46,86.69 ; 77.01,77.25 77.15,77.39 v2(83.23,77.39) ; v1(64.71,87.4) 64,86.69 ; 64,86.69 64,88.03 63.97,88.06 C24.2 64.87,88.8 65.06,88.99 v1(65.28,88.99) ; 49.23,86.69 49.18,86.74 48.95,86.74 48.5,87.19 48.5,88.14 v2(49.31,88.94)
  TOP w0.7: v2(30.46,69.15) 30.67,68.94 30.67,68.2 ; v2(56.28,45.23) 51.14,40.1 50.5,40.1 43.96,33.56 v2(43.96,32.71) ; v2(18.11,79.9) 19.72,79.9 19.74,79.88 30.7,79.88 30.72,79.9 ; 30.67,67.13 28.58,67.13 28.57,67.15 v2(27.71,67.15)
  TOP w0.8: v2(56.28,45.23) 58.45,47.4 v2(59.51,47.4) 65.63,47.4 67.09,48.86
  TOP w0.9: 67.11,33.85 67.11,47.18
  TOP w1: 67.11,47.18 67.11,48.83 67.09,48.86
  TOP w1.2: v1(67.54,52.77) 68.06,52.77
  TOP w1.5: 52.25,86.69 66.28,86.69 66.94,86.04 69.17,86.04 69.82,86.69 73.52,86.69 77.01,83.2 77.01,61.68 76.27,60.94 76.23,60.94 69.43,54.14 C83.1 ; 52.25,86.69 34.41,86.69 30.72,83 30.72,68.25 30.67,68.2 v2(30.67,62.99) 30.67,61.59 v2(32.65,59.61) 32.65,55.72 30.11,53.18 30.11,48.75 28.79,47.42 ; 52.25,86.69 49.02,83.46 49.02,77.59 48.96,77.53 48.96,74.76 49.02,74.7 49.02,73.89 49.02,73.89 49.02,72.89 48.96,72.83 48.96,69.8 48.28,69.12 48.28,65
  TOP w2: 67.09,48.86 C83.1
  LOGIC_PLANE w0.2: v1(59.87,56.4) 59.06,57.21 59.06,57.25 v1(57.71,58.6)
  LOGIC_PLANE w0.4: v2(61.51,54.21) 62.72,54.21 63.13,53.8 63.18,53.8 v1(63.7,53.28)
  BOTTOM w0.152: 74.6,88.5 v2(75.33,87.77) ; v2(64.48,85.07) 64.11,85.44 64.01,85.44 ; R146.1 v2(73.36,39.85) ; v1(75.54,85.43) 75.5,85.39 C29.2 ; 31.01,75.15 v2(31.06,75.2) ; 30.66,78.45 30.71,78.4 v2(31.11,78.4) ; 26.55,67.18 J17.16 ; R149.1 91.06,53.75 v1(91.11,53.8) ; C120.2 v1(59.26,86.75) ; R170.1 v1(77.51,66.35)
  BOTTOM w0.16: 64.76,84.69 64.76,83.43 64.86,83.33
  BOTTOM w0.18: J23.1 92.94,75 C109.2
  BOTTOM w0.2: 64.01,85.44 64.76,84.69 ; U19.15 C74.1 ; 63.62,30.47 63.62,31.1 63.61,31.1 C44.1 ; C78.1 30.67,78.2 31.28,78.2 ; U19.81 C71.1 ; 63.36,59.55 63.36,59.49 C114.2 ; U19.1 31.16,61.2 30.96,61 C69.1 ; C110.1 57.75,46.61 ; C73.1 45.41,66.9 45.21,66.7 U19.75 ; U27.30 56.86,60.69 56.31,60.14 56.31,59.16 C106.1 C115.2 57.25,59.06 v1(57.71,58.6) ; U27.30 56.91,61.67 56.91,62 ; U27.30 v1(56.86,62.91) ; v2(70.81,56.75) 70.86,56.8 70.87,56.8 R185.2 ; C121.2 65.01,84.74 64.91,84.64 64.91,83.38 64.86,83.33 U27.95 ; v2(31.11,83.4) 31.06,83.45 31.01,83.45 ; U19.3 C70.1 ; U19.55 45.11,76.7 45.56,76.25 C77.1 C76.1 ; v1(59.87,56.4) 59.87,56.04 60.32,55.59 60.37,55.59 60.64,55.32 Y2.4 ; v1(75.11,58.4) 75.11,56.4 75.52,55.99 v1(85.66,55.99) ; R143.2 90.62,56.11 v1(90.91,56.4) ; U19.9 v2(30.37,65.2)
  BOTTOM w0.25: v1(77.86,71.75) 77.07,71.75 ; 75.85,70 75.65,70.2 v1(75.51,70.2) ; 75.85,70 C107.2 ; 75.85,70 U27.131 ; 33.51,81.2 33.94,81.2 34.71,80.42 34.71,78.97 33.94,78.2 U19.35 31.28,78.2 ; 33.51,81.2 33.59,81.27 33.68,81.27 33.89,81.48 33.89,82 33.69,82.2 U19.43 ; 33.51,81.2 U19.41 ; U19.43 33.04,83.07 31.94,84.17 30.85,84.17 30.67,84.35 C80.1 ; U19.43 32.62,82.2 31.37,83.45 31.16,83.45 v2(31.11,83.4) ; U19.29 31.13,75.2 31.08,75.15 C75.1 ; v1(77.71,64) 77.56,63.85 R179.1 ; 63.36,59.55 U27.17 ; 30.66,78.45 C78.1 ; v1(75.32,62.63) 75.75,62.2 C108.2 ; C81.1 31.01,83.45 ; C120.2 59.5,86.21 59.91,85.8 59.91,85.06 59.71,84.86 59.71,84.75 59.51,84.55 59.51,84.35 59.36,84.2 U27.84 ; U19.49 45.06,79.7 45.56,80.2 v1(46.15,80.2) ; 71.46,85.28 v2(70.83,84.64)
  BOTTOM w0.3: C110.1 55.81,46.7 53.91,44.8 51.91,44.8 50.48,46.23 42.28,46.23 41.91,46.6 41.91,49.2 v1(43.91,51.2) 44.48,51.2 46.3,53.03 C68.1 ; 46.28,64.47 46.15,64.34 C71.1 ; 46.28,64.47 46.28,66.62 C73.1 ; 46.28,64.47 47.05,65.24 v2(48.31,65.24) ; v2(53.21,80.7) 52.91,81 U27.72 C119.2 ; v1(63.7,53.28) 63.71,53.28 63.71,53.64 C82.2 64.01,53.94 64.34,54.27 64.6,54.53 64.6,58.25 C114.2 ; C117.2 v1(49.81,71) 50.48,71 50.48,71 51.14,71 51.14,71 U27.52 ; U6.8 76.41,88.12 76.66,87.87 76.66,87.31 76.81,87.16 v2(76.91,87.16) ; U27.144 74.45,63.5 v1(75.32,62.63) ; 77.07,71.75 76.97,71.65 C113.2 ; C126.1 59.91,53.94 59.97,54 R183.1 60.84,54.2 60.85,54.21 61.3,54.21 ; U27.39 C116.2 ; U27.121 C123.2 ; U27.108 71.36,84.25 71.48,84.37 71.48,84.92 71.46,84.94 C122.2 ; U27.62 C118.2
  BOTTOM w0.4: v2(31.11,84.8) 30.91,84.8 30.46,84.35 ; v2(64.59,31.32) 63.73,30.47 63.62,30.47 U12.8 ; 42.31,29.2 42.31,29.4 v1(42.71,29.8) ; U11.8 69.67,31.05 v2(69.12,31.6) ; C97.1 58.44,49 57.75,48.31 C110.1 ; v2(48.31,65.24) 48.66,65.24 49.27,64.64 C116.2 ; v2(88.11,91.2) 88.61,90.7 88.61,90.19 89.8,89 U28.6 ; C120.2 R169.1 R167.1 ; U20.8 65.12,52.48 64.79,52.8 64.79,53.16 C82.2 ; Y2.4 60.91,55 60.91,54.6 61.3,54.21 v2(61.51,54.21) ; v2(28.91,47.4) 29.52,47.4 29.96,47.84 30.35,47.84 30.36,47.85 34.76,47.85 35.51,48.6 v1(36.31,48.6) ; U6.8 75.13,88.51 75.12,88.5 C30.1
  BOTTOM w0.5: C41.1 71.86,33.7 v2(71.91,33.75) ; C42.1 v2(69.12,31.6) ; J17.5 18.13,79.88 v2(18.11,79.9) ; v2(56.28,45.23) 56.77,45.72 56.85,45.72 57.75,46.61 ; v1(65.28,88.99) 65.48,88.99 U3.8 ; v2(32.65,59.61) 32.12,60.14 31.82,60.14 31.46,60.5 30.87,60.5 C69.1 ; 67.11,50.2 C99.1 ; C74.1 30.37,69.06 v2(30.46,69.15) ; C15.1 v2(49.26,87.5) 49.26,87.57 49.25,87.58 C16.1 49.25,88.54 ; U10.8 75.67,30.8 75.17,31.3 v2(75.16,31.3) ; v2(76.92,77.39) 76.1,76.57 C123.2 ; v1(64.71,87.4) 64.39,87.72 C22.1 ; v2(27.71,67.15) 27.69,67.13 27.48,67.13 27.43,67.18 26.55,67.18 26.96,67.58 26.96,67.7 v2(27.41,68.15) ; v2(83.23,77.39) J18.7 ; v2(30.67,62.99) 30.67,62.8 30.37,62.5 C70.1
  BOTTOM w0.7: v2(49.31,88.94) 49.31,88.6 49.07,88.36 48.91,88.36 48.72,88.17 U2.1 ; v2(43.96,32.71) 43.96,30.85 42.31,29.2 v2(42.31,27.03) ; J17.33 J17.34 26.55,44.32 28.31,46.07 28.31,46.8 v2(28.91,47.4) v2(30.06,48.55) v1(30.11,48.6)
  BOTTOM w0.8: C110.1 58.81,46.7 v2(59.51,47.4)
  BOTTOM w1: C83.1 67.06,51.77 U20.8
  BOTTOM w1.2: 68.91,54.2 v1(68.71,54) v1(68.31,53.6) v1(67.91,53.2) 67.6,52.89 67.6,52.84 v1(67.54,52.77) 67.09,52.32 C83.1
  BOTTOM w1.3: L5.2 67.01,49.85 C99.1 67.11,50.45 67.11,51.77
  BOTTOM w1.5: 67.11,51.77 C83.1
VDD_CLT: length 29.9
  TOP w0.152: R6.2 33.05,93.18 C6.2
  TOP w0.5: v2(47.72,94.87) 47.72,94.12 47.68,94.08 C14.1 ; C5.1 41.58,95.45 41.61,95.48 J4.3 ; R6.2 35.09,94.05 36.81,95.77 36.81,95.82 J2.3
  BOTTOM w0.3: J2.3 36.63,95.64 C129.1
  BOTTOM w0.5: 47.66,94.81 v2(47.72,94.87) ; 47.66,94.81 47.66,94.86 45.79,96.72 J4.3 J2.3 ; 47.66,94.81 U2.16
VDD_EXT: length 12.4
  TOP w0.4: J25.1 93.63,94.52 92.63,94.52 v2(87.71,89.6)
  BOTTOM w0.4: U28.8 87.25,89.14 v2(87.71,89.6)
BOOT0: length 8.6
  BOTTOM w0.2: R171.1 82.8,66.17 78.34,66.17 77.62,66.89 76.59,66.89 R170.2
CLT_CS1: length 14.1
  TOP w0.2: v2(43.51,95) 43.51,92.9 42.41,91.8 34.22,91.8 R1.2
  BOTTOM w0.4: U2.13 43.84,94.6 43.51,94.94 v2(43.51,95)
CLT_IN1: length 4.7
  TOP w0.2: 28.8,99.25 28.8,99.92 29.43,100.55 30.96,100.55 31.11,100.7 C7.2 R7.2
CLT_IN2: length 3.3
  TOP w0.2: 28.3,99.25 28.3,100.03 29.02,100.75 29.25,100.98 29.25,101.03 C8.2 R9.2
CLT_IN3: length 2.9
  TOP w0.2: 27.8,99.25 27.8,100.61 27.91,100.72 C9.2 R11.2
CLT_IN4: length 2.9
  TOP w0.2: 27.3,99.25 27.3,100.51 27.11,100.7 R12.2 C10.2
CLT_IN5: length 3.3
  TOP w0.2: 26.3,99.25 26.3,100.16 25.77,100.69 25.77,101.03 R14.2 24.71,101.34 C12.2
CLT_IN6: length 4.3
  TOP w0.2: C13.2 R17.2 23.86,100.95 24.06,100.75 24.8,100.75 24.96,100.75 25.12,100.75 25.8,100.07 25.8,99.25
CLT_IN7: length 5.4
  TOP w0.2: 21.51,101.34 C17.2 R19.2 22.31,100.77 22.68,100.4 24.79,100.4 25.3,99.89 25.3,99.25
CLT_IN8: length 6.2
  TOP w0.2: 24.8,99.25 24.8,99.81 24.66,99.95 21.89,99.95 20.76,101.08 R22.2 C18.2
CLT_MISO: length 22.2
  TOP w0.2: 36.45,89.54 35.61,88.69 29.52,88.69 28.61,89.6 C1.1 28.61,90.19 R4.2 27.72,90.19
  TOP w0.22: 36.45,89.54 v1(36.81,89.9)
  BOTTOM w0.18: 38.61,91.2 40.04,92.63 U2.10
  BOTTOM w0.2: v1(36.81,89.9) 38.12,91.2 38.61,91.2
  BOTTOM w0.25: TP1.1 37.51,94.1 37.51,95 38.11,95.6 39.13,95.6 40.04,94.69 U2.10
CLT_MOSI: length 22.1
  TOP w0.2: v2(46,95.34) 46,92.94 43.91,90.85 34.76,90.85 33.46,89.55 30.51,89.55 30.31,89.75 R3.2
  BOTTOM w0.4: v2(46,95.34) 46.31,95.03 46.31,93.41 46.39,93.33
CLT_SCK: length 18
  TOP w0.2: R2.2 33.46,90.15 34.66,91.35 43.11,91.35 45.11,93.35 v2(45.11,95.2)
  BOTTOM w0.4: U2.14 45.12,95.19 v2(45.11,95.2)
DI_FLT_Q1_1: length 36.3
  BOTTOM w0.16: 68.39,29.89 68.39,37.48 73.39,42.48 73.39,58.12 72.02,59.49 70.76,59.49 70.76,59.49 70.58,59.49 69.36,60.71 U27.5
DI_FLT_Q1_2: length 37
  POWER PLANE w0.2: v1(71.71,54.6) 71.71,58.41 70.37,59.75 v1(68.86,59.75)
  BOTTOM w0.2: U27.7 68.36,60.25 v1(68.86,59.75) ; v1(71.71,54.6) 73.01,53.3 73.01,42.7 67.12,36.81 U11.6
DI_FLT_Q1_3: length 88.9
  POWER PLANE w0.16: 64.3,73.62 67.17,76.49 v1(69.84,76.49) ; 54.21,51.78 54.21,50.58 46.07,42.44
  POWER PLANE w0.2: 64.3,73.62 64.3,59.84 57.44,52.98 55.4,52.98 54.21,51.78 ; 46.07,42.44 v1(44.5,40.87)
  BOTTOM w0.2: U27.118 70.42,76.5 ; 70.42,76.5 70.41,76.49 70.29,76.49 ; 70.42,76.5 70.3,76.5 70.29,76.49 ; 70.29,76.49 v1(69.84,76.49) ; 74.39,29.84 74.39,29.2 73.79,28.6 57.51,28.6 47.81,38.3 46.01,38.3 44.5,39.81 v1(44.5,40.87)
DI_FLT_Q1_4: length 41.3
  POWER PLANE w0.16: 73.9,42.29 73.9,56.33 74.29,56.72 74.29,61.58 74.25,61.62 74.25,65.96 75.18,66.89 v1(75.18,67.52)
  POWER PLANE w0.17: v1(73.91,41.8) 73.91,42.28 73.9,42.29
  BOTTOM w0.16: v1(75.18,67.52) 74.71,68 74.41,68 74.39,68.02 74.03,68.02 74.01,68 U27.135
  BOTTOM w0.17: U10.6 73.12,34.38 72.51,35 72.51,39.48 72.5,39.49 72.5,40.21 72.51,40.22 72.51,40.4 v1(73.91,41.8)
DI_FLT_Q1_FLT: length 60.4
  POWER PLANE w0.16: v1(63.19,34.57) 64.59,34.57 72.51,42.5 72.51,61.96 72.52,61.97 72.52,74.46 68.97,78.01 68.6,78.01 v1(68.26,78.35)
  BOTTOM w0.16: v1(68.26,78.35) 67.36,79.25 U27.100
  BOTTOM w0.2: v1(63.19,34.57) 62.34,33.73 U12.7
DI_FLT_Q1_OL: length 63
  POWER PLANE w0.16: v1(61.42,33.31) 62.05,33.95 64.61,33.95 72.82,42.16 72.82,61.83 72.83,61.84 72.83,74.59 68.89,78.53 68.88,78.53 68.41,79 v1(66.71,79)
  BOTTOM w0.2: v1(61.42,33.31) 61.08,32.97 U12.6 ; v1(66.71,79) 66.71,80.45 66.86,80.6 U27.99
DI_I1_1: length 35.3
  POWER PLANE w0.152: 73.84,76.66 73.84,84.54 71.72,86.66
  POWER PLANE w0.16: 73.84,76.66 73.84,67.41 73.84,67.41 73.84,66.67 73.86,66.65 v1(73.86,61.4)
  POWER PLANE w0.25: v1(67.31,87.22) 67.87,86.66 71.72,86.66
  BOTTOM w0.152: U27.1 71.36,61.14 71.57,60.93 73.39,60.93 v1(73.86,61.4) ; U3.7 67.28,87.44 67.31,87.4 v1(67.31,87.22)
DI_I1_2: length 49.1
  POWER PLANE w0.152: v1(68.71,87.14) 68.71,88.04 69.79,89.12 77.89,89.12 78.33,88.68 78.33,86.21 79.2,85.34 79.2,63.39 78.87,63.06 78.87,62.9 78.59,62.62 v1(78.59,62.6)
  BOTTOM w0.152: U3.6 68.55,87.56 68.71,87.4 v1(68.71,87.14) ; U27.2 70.86,60.71 71.07,60.51 76.97,60.51 78.59,62.12 v1(78.59,62.6)
DI_I1_3: length 37.5
  POWER PLANE w0.16: v1(77.57,60.4) 78.16,60.98 78.16,62.78 78.89,63.51 78.89,85.21 77.74,86.36 v2(77.74,87.05)
  BOTTOM w0.152: v2(77.74,87.05) 77.74,87.12 77.67,87.19 U6.7
  BOTTOM w0.16: U27.3 70.36,60.76 70.92,60.2 77.37,60.2 v1(77.57,60.4)
DI_I1_4: length 38.8
  POWER PLANE w0.16: v2(78.91,87.05) 79.5,86.46 79.5,63.26 79.17,62.93 79.17,62.01 v1(78.84,61.67)
  BOTTOM w0.152: v2(78.91,87.05) 78.91,87.2 78.95,87.23 U6.6
  BOTTOM w0.16: U27.4 69.86,60.83 70.89,59.8 77.71,59.8 78.84,60.92 v1(78.84,61.67)
DI_Q0_FLT: length 60.5
  TOP w0.16: R78.2 33.64,32.94 34.08,32.94 v1(34.09,32.95)
  POWER PLANE w0.16: 35.93,33.34 37.61,33.34 56.61,52.34 57.71,52.34 64.94,59.57 64.94,67.86 67.63,70.55 v1(68.11,70.55)
  POWER PLANE w0.17: 35.93,33.34 34.49,33.34 v1(34.09,32.95)
  BOTTOM w0.16: v1(68.11,70.55) 68.56,71 U27.129
DI_Q0_PGOOD: length 63.9
  TOP w0.16: R82.1 31.04,31.44 v1(31.04,31.12)
  POWER PLANE w0.16: v1(71.31,71.5) 70.31,71.5 65.25,66.44 65.25,59.44 57.84,52.03 56.74,52.03 37.74,33.03 37.7,33.03 36.32,31.65 31.57,31.65 v1(31.04,31.12)
  BOTTOM w0.16: U27.128 v1(71.31,71.5)
DO_LCD_BL_CTRL: length 42.5
  POWER PLANE w0.18: v1(54.86,60.62) 55.3,61.06 59.28,61.06 59.31,61.03 59.95,61.03 60.13,60.85 60.13,60.11 60.39,59.85 v1(60.88,59.85) ; v1(50.06,44.74) 50.6,45.28 50.6,45.4 56.83,51.63 57.92,51.63 65.96,59.67 v1(65.96,60.63)
  LOGIC_PLANE w0.18: v1(65.96,60.63) 63.34,60.63 62.56,59.85 v1(60.88,59.85)
  BOTTOM w0.18: v1(50.06,44.74) R84.1 ; U27.34 54.82,61.58 54.82,61.09 54.86,61.05 v1(54.86,60.62)
  BOTTOM w0.3: 54.86,61.05 U27.34
DO_Q0_EN: length 45.9
  TOP w0.16: R64.2 45.81,33.3 v1(45.71,33.4)
  LOGIC_PLANE w0.16: v1(53.39,66.79) 52,65.4 51.31,65.4 50.83,64.91 50.78,64.91 50.66,64.8 49.91,64.8 47.11,62 47.11,59.94 47.06,59.89 47.06,59.53 47.11,59.48 47.11,58.8 38.62,50.3 38.62,46.83 39.91,45.53 39.91,39.4
  LOGIC_PLANE w0.2: 39.91,39.4 39.91,39.2 v1(45.71,33.4)
  BOTTOM w0.16: U27.45 52.91,67.5 53.05,67.36 53.05,67.13 v1(53.39,66.79)
DO_Q1_1: length 89.1
  POWER PLANE w0.152: v2(84.11,33.85) 80.46,37.5 80.46,40.09 80.46,40.09 80.46,88.77 79.03,90.2 59.31,90.2 v1(58.91,89.8)
  BOTTOM w0.152: v1(58.91,89.8) 56.91,89.8 56.14,89.03 56.14,87.62 56.11,87.6 56.11,85.8 55.88,85.58 55.88,85.57 55.38,85.07 55.38,84.99 55.36,84.98 U27.76 ; R32.2 84.06,33.8 v2(84.11,33.85)
DO_Q1_2: length 90.4
  POWER PLANE w0.152: v2(87.71,33.85) 80.91,40.65 80.91,86.41 80.89,86.42 80.89,88.77 79.09,90.57 58.48,90.57 57.05,89.14 57.05,88.94 v1(56.71,88.6)
  BOTTOM w0.152: U27.80 57.36,84.35 56.91,84.8 56.91,87.92 56.71,88.12 v1(56.71,88.6)
  BOTTOM w0.2: v2(87.71,33.85) 87.81,33.75 R36.2
DO_Q1_3: length 55.1
  POWER PLANE w0.152: 74.6,38.06 73.34,39.32 73.14,39.32 72.83,39.63 72.83,40.07 73.12,40.37 73.12,61.71 73.13,61.71 73.13,74.72 69.02,78.84 69,78.84 66.93,80.91 66.7,80.91 v1(66.36,81.25)
  POWER PLANE w0.16: v2(77.81,33.85) 77.81,34.85 74.6,38.06
  BOTTOM w0.152: R46.2 v2(77.81,33.85)
  BOTTOM w0.2: U27.98 v1(66.36,81.25)
DO_Q1_4: length 51.7
  POWER PLANE w0.16: v1(72.21,79.1) 72.21,77.85 73.51,76.55 73.51,61.66 73.43,61.58 73.43,61.22 73.48,61.17 73.48,41.62 75.75,39.35 76.78,39.35 81.64,34.49 v1(81.64,33.88)
  BOTTOM w0.16: v1(81.64,33.88) 81.64,33.09 R48.2
  BOTTOM w0.2: U27.113 72.51,79 72.41,79.1 v1(72.21,79.1)
ENCQ: length 47.4
  TOP w0.2: v1(89.91,84.76) 89.91,84.26 87.77,82.12 87.77,73.55 89.02,72.3 v1(91.19,72.3)
  POWER PLANE w0.16: v1(71.67,92.2) v1(82.71,92.2)
  LOGIC_PLANE w0.16: 89.2,85.11 83.44,90.88 83.44,91.47 83.02,91.88 83.02,91.89 v1(82.71,92.2)
  LOGIC_PLANE w0.2: v1(89.91,84.76) 89.56,85.11 89.2,85.11
  BOTTOM w0.152: R118.1 v1(91.19,72.3)
  BOTTOM w0.16: R158.2 67.81,87.3 67.94,87.43 67.94,87.78 67.83,87.9 67.83,89.25 67.83,89.32 70.71,92.2 v1(71.67,92.2)
  BOTTOM w0.2: v1(89.91,84.76) 90.1,84.76 90.31,84.97 90.31,85.14 R115.1
ENL+: length 133.6
  POWER PLANE w0.16: v1(71.41,91.1) 71.75,91.44 72.32,91.44 72.33,91.43 82.34,91.43 86.81,86.96 86.81,51.16 86.81,51.15 86.81,49.1 88.16,47.75 88.16,46.12 89.24,45.04 v1(90.02,45.04)
  LOGIC_PLANE w0.2: v1(39.45,46.86) 40.96,45.35 44.54,45.35 44.54,45.36 45,45.36 46.36,44 v1(50.71,44) ; v1(66.21,43) 74.01,43 74.71,43.7 v2(76.46,43.7)
  BOTTOM w0.16: v1(71.41,91.1) 71.41,90.62 71.31,90.52 71.31,88.06 R159.2 ; R139.1 90.02,45 v1(90.02,45.04)
  BOTTOM w0.2: v2(76.46,43.7) 77.21,43.7 77.91,43 89.22,43 R139.1 ; R188.1 33.51,42.4 38.85,47.74 R98.2 39.11,47.2 v1(39.45,46.86) ; v1(50.71,44) 51.71,43 v1(66.21,43)
FLT: length 13.7
  TOP w0.2: U8.10 67.95,21.48 67.91,21.45 63.89,21.45 63.31,20.86 v1(63.31,20.2)
  TOP w0.3: D21.C 58.26,23.8 59.61,22.45 60.18,22.45 60.79,21.84 60.83,21.84 61.29,21.38 62.13,21.38 v1(63.31,20.2)
  BOTTOM w0.25: v1(63.31,20.2) 62.91,20.6 62.75,20.6 R61.2
FMC_ADD.A0: length 46.9
  POWER PLANE w0.152: v1(59.51,65.77) 57.8,65.77 55.76,63.73 55.76,63.66 55.51,63.41 55.44,63.41 54.43,62.4 45.26,62.4 39.16,68.5 39.16,70.6 38.26,71.5 38.26,73.07 38.71,73.52 v1(38.71,74.4)
  BOTTOM w0.152: v1(59.51,65.77) 63.38,65.77 66.86,62.29 U27.10 ; v1(38.71,74.4) 38.71,73.52 38.39,73.2 U19.25
FMC_ADD.A1: length 44.4
  POWER PLANE w0.152: v1(59.51,65.22) 59.03,65.22 59.01,65.2 57.73,65.2 55.64,63.11 55.61,63.11 54.6,62.1 45.13,62.1 38.86,68.37 38.86,68.42 38.84,68.45 38.84,70.1 38.81,70.13 38.81,70.35 37.88,71.28 37.88,73.49 v1(38.11,73.71)
  BOTTOM w0.152: U19.26 33.89,73.7 33.9,73.71 v1(38.11,73.71) ; U27.11 66.36,62.37 63.26,65.47 60.2,65.47 60.13,65.4 59.74,65.4 59.56,65.22 v1(59.51,65.22)
FMC_ADD.A2: length 49.4
  POWER PLANE w0.152: v1(60.11,64.95) 59.28,64.12 59.28,63.47 57.61,61.8 44.91,61.8 38.36,68.35 38.36,70.15 37.48,71.03 37.48,74.27 v1(39.16,75.95)
  BOTTOM w0.152: U27.12 65.86,62.44 63.13,65.16 60.8,65.16 60.59,64.95 v1(60.11,64.95) ; v1(39.16,75.95) 37.41,74.2 U19.27
FMC_ADD.A3: length 28.1
  POWER PLANE w0.152: v1(62.91,64.6) 62.5,65.01 62.02,65.01 53.48,73.55 v1(50.71,73.55)
  BOTTOM w0.152: U19.60 44.82,74.2 46.78,72.23 48.14,72.23 49.19,73.28 50.54,73.28 50.71,73.45 v1(50.71,73.55) ; v1(62.91,64.6) 63.11,64.4 63.36,64.4 63.37,64.4 63.47,64.4 65.36,62.51 U27.13
FMC_ADD.A4: length 27.1
  POWER PLANE w0.152: v1(61.89,64.58) 60.31,66.16 60.31,66.23 58.81,67.73 58.75,67.73 53.54,72.94 51.4,72.94 51.39,72.95 v1(50.91,72.95)
  BOTTOM w0.152: v1(50.91,72.95) 50.51,72.95 50.49,72.98 49.31,72.98 48.27,71.93 46.66,71.93 44.89,73.7 U19.61 ; U27.14 64.86,62.48 63.24,64.1 62.37,64.1 v1(61.89,64.58)
FMC_ADD.A5: length 26.5
  POWER PLANE w0.152: v1(61.39,64.36) 60.01,65.74 60.01,66.1 58.69,67.43 58.55,67.43 53.63,72.35 51.41,72.35 51.36,72.4 51.04,72.4 50.91,72.53 50.73,72.53 50.71,72.55 v1(50.31,72.55)
  BOTTOM w0.152: U27.15 64.36,62.55 63.11,63.8 61.95,63.8 v1(61.39,64.36) ; U19.62 44.96,73.2 46.53,71.63 48.39,71.63 49.32,72.55 v1(50.31,72.55)
FMC_ADD.A6: length 9.8
  POWER PLANE w0.16: v1(45.91,71.65) 45.91,71.17 45.88,71.14 45.88,70.21 46.11,69.97 49.76,69.97 49.78,69.95 v1(50.26,69.95)
  BOTTOM w0.16: v1(45.91,71.65) 44.86,72.7 U19.63
  BOTTOM w0.18: v1(50.26,69.95) 50.75,69.95 50.8,70 U27.50
FMC_ADD.A7: length 12
  LOGIC_PLANE w0.152: v1(52.98,71.5) 50.71,71.5 49.9,72.3 43.84,72.3 43.73,72.2 v1(43.26,72.2)
  BOTTOM w0.152: U27.53 v1(52.98,71.5) ; v1(43.26,72.2) U19.64
FMC_ADD.A8: length 10.8
  LOGIC_PLANE w0.152: v1(50.07,71.54) 49.59,71.54 49.59,71.53 46.39,71.53 46.09,71.22 45.73,71.22 45.46,71.5 v1(42.96,71.5)
  BOTTOM w0.152: v1(50.07,71.54) 50.77,71.54 51.24,72 U27.54 ; v1(42.96,71.5) 43.11,71.65 43.36,71.65 43.41,71.7 U19.65
FMC_ADD.A9: length 9.2
  POWER PLANE w0.152: v1(47.71,71) 47.71,71.8 47.97,72.06 50.22,72.06 50.26,72.1 v1(50.73,72.1)
  BOTTOM w0.152: v1(50.73,72.1) 50.73,72.35 50.89,72.5 U27.55 ; v1(47.71,71) 47.71,71.05 47.53,71.23 46.73,71.23 46.71,71.2 U19.66
FMC_ADD.A10: length 24.6
  LOGIC_PLANE w0.2: v1(53.21,74.6) 52.71,74.6 52.51,74.8 v1(39.51,74.8)
  BOTTOM w0.16: U27.56 52.91,73 53.46,73.55 53.46,74.35 v1(53.21,74.6)
  BOTTOM w0.2: U19.24 38.41,72.7 39.51,73.8 v1(39.51,74.8)
FMC_ADD.A11: length 25.9
  LOGIC_PLANE w0.2: v1(52.99,74) 53.47,73.52 53.47,71.2 53.27,71 50.7,71 50.14,70.44 47.75,70.44 47.32,70.01 45.9,70.01 44.91,71 35.06,71 34.76,71.3 34.76,71.3 v1(34.71,71.35)
  BOTTOM w0.2: U27.57 52.71,73.5 52.99,73.78 v1(52.99,74) ; U19.21 34.02,71.2 34.17,71.35 v1(34.71,71.35)
FMC_ADD.BA_0: length 35.2
  POWER PLANE w0.152: v1(39.11,71.85) 39.11,72.38 50.08,83.35 61.33,83.35 v1(61.86,83.88)
  BOTTOM w0.152: v1(61.86,83.88) U27.89 ; U19.22 34.42,71.7 34.57,71.85 v1(39.11,71.85)
FMC_ADD.BA_1: length 35.6
  POWER PLANE w0.152: v1(39.84,72.38) 42.58,75.12 43.19,75.12 43.44,75.37 43.44,75.93 50.51,83 61.24,83 v1(62.36,81.88)
  BOTTOM w0.152: v1(39.84,72.38) 39.03,72.38 38.86,72.2 U19.23 ; U27.90 v1(62.36,81.88)
FMC_CTRL.NBL0: length 47
  POWER PLANE w0.17: v1(39.91,68.4) 45.59,62.72 53.38,62.72 56.78,66.11 57.62,66.11 v1(58.51,67)
  BOTTOM w0.17: U19.16 34.61,68.7 35.09,68.22 35.53,68.22 37.41,70.1 38.21,70.1 v1(39.91,68.4) ; v1(58.51,67) 59,67 59.2,67.2 63.71,67.2 65.91,65 U27.141
FMC_CTRL.NBL1: length 33.9
  LOGIC_PLANE w0.18: v1(61.51,66.6) 60.51,67.6 54.11,67.6 53.74,67.23 53.21,67.23 52.98,67 44.71,67 v1(42.91,68.8)
  BOTTOM w0.18: U27.142 65.81,64.5 63.71,66.6 v1(61.51,66.6) ; v1(42.91,68.8) 43.01,68.7 U19.71
FMC_CTRL.SDCKE0: length 20.7
  POWER PLANE w0.2: v1(46.31,70.6) 46.56,70.35 49.86,70.35 49.95,70.44 54.77,70.44 56.77,68.44 56.77,67.07 v1(57.29,66.55)
  BOTTOM w0.2: v1(57.29,66.55) 57.29,65.88 57.37,65.8 57.37,65.43 57.35,65.41 57.35,62.56 57.36,62.55 U27.29 ; v1(46.31,70.6) 45.15,70.6 45.05,70.7 U19.67
FMC_CTRL.SDCLK: length 31.3
  POWER PLANE w0.152: v1(43.26,70.2) 43.99,70.93 43.99,74.98 44.06,75.05 44.06,75.45 51.31,82.7 54.36,82.7 54.71,82.35 61.16,82.35 62.11,81.4 v1(63.86,81.4)
  BOTTOM w0.152: v1(63.86,81.4) U27.93 ; v1(43.26,70.2) U19.68
FMC_CTRL.SDNCAS: length 59.5
  POWER PLANE w0.152: v1(56.31,85.4) 45.31,85.4 35.41,75.5 35.41,70.4 v1(34.71,69.7)
  LOGIC_PLANE w0.152: v1(61.01,81.4) 61.01,81.88 57.49,85.4 v1(56.31,85.4)
  BOTTOM w0.152: U27.132 67.81,69.5 61.01,76.3 v1(61.01,81.4) ; v1(34.71,69.7) U19.18
FMC_CTRL.SDNE0: length 20.7
  TOP w0.16: v1(34.55,70.71) 34.88,70.37 34.88,70.28 37.71,67.45 44.91,67.45 45.06,67.6 v1(46.51,67.6)
  BOTTOM w0.152: v1(46.51,67.6) 47.89,67.6
  BOTTOM w0.16: 47.89,67.6 48.11,67.6 48.71,67 U27.44
  BOTTOM w0.18: U19.20 33.93,70.7 33.94,70.71 v1(34.55,70.71)
